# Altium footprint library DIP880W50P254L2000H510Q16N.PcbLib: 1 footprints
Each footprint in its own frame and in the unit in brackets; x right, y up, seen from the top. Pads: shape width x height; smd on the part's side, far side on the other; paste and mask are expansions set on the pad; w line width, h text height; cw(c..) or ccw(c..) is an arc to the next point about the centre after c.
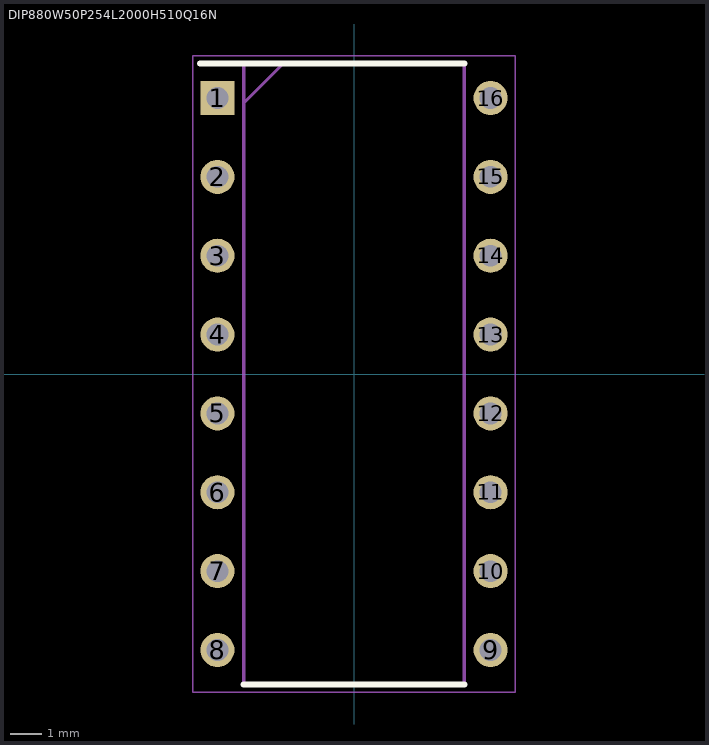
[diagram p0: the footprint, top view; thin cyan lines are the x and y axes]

## DIP880W50P254L2000H510Q16N [mm]
pads (16):
  rect 1.1x1.1 / inner round 1.1 / far side rect 1.1x1.1 hole 0.7: 1(-4.4,8.89)
  round 1.1 hole 0.7: 2(-4.4,6.35) 3(-4.4,3.81) 4(-4.4,1.27) 5(-4.4,-1.27) 6(-4.4,-3.81) 7(-4.4,-6.35) 8(-4.4,-8.89) 9(4.4,-8.89) 10(4.4,-6.35) 11(4.4,-3.81) 12(4.4,-1.27) 13(4.4,1.27) 14(4.4,3.81) 15(4.4,6.35) 16(4.4,8.89)
Top Overlay:
  lines w0.2: -4.95,10 3.55,10 ; -3.55,-10 3.55,-10
Mechanical 15:
  lines w0.1: -3.55,8.73 -2.28,10 ; -3.55,-10 3.55,-10 3.55,10 -3.55,10 -3.55,-10
Mechanical 20:
  lines w0.05: -5.2,-10.25 5.2,-10.25 5.2,10.25 -5.2,10.25 -5.2,-10.25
